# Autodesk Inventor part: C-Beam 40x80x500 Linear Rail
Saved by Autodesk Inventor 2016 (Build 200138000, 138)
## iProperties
Created: 2015-11
Part Number: C-Beam 40x80x500 Linear Rail
Material: Generic
Document SubType Name: Modeling
Designer: John
Density: 1 g/cm^3
Appearance: Default
Author: John
Revision Number: ANY
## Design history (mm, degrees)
feature "Boss-Extrude1"
body "Solid1"
